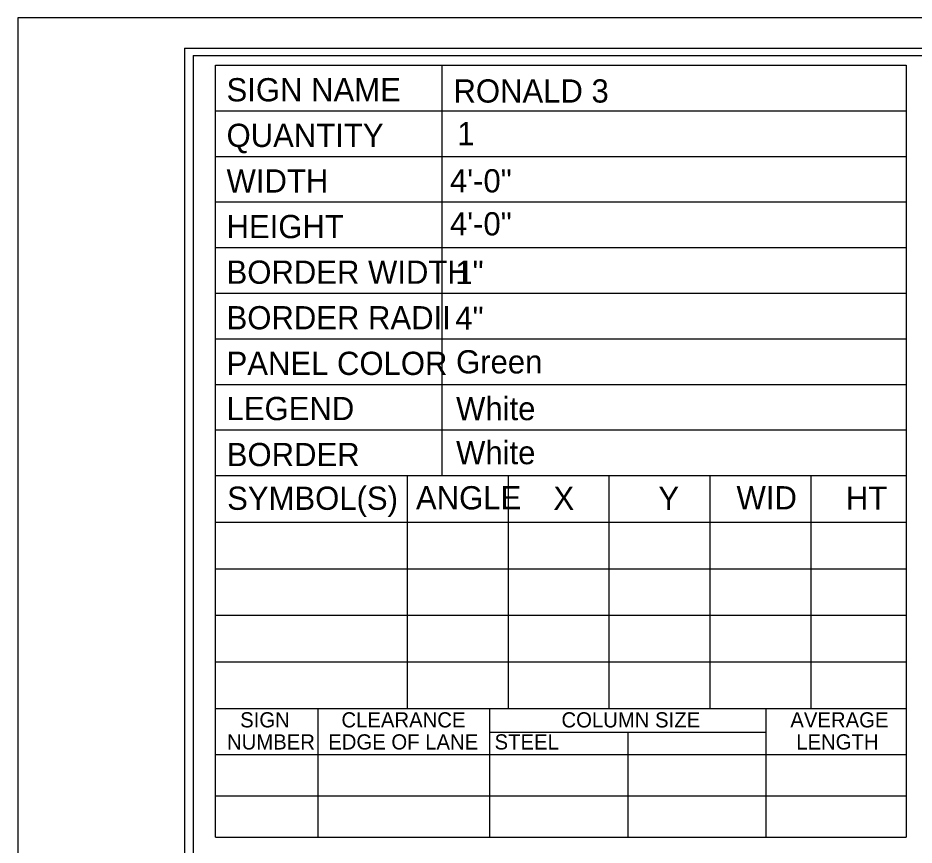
# Model space of a CAD drawing. Extents: x 17890628 to 17890844, y 17897693 to 17898031.
# Drawn here: x 17890700.47 to 17890726.2, y 17897976.07 to 17897999.81 of the extents above; entities that cross this region are included whole.
import ezdxf

# ---------------------------------------------------------------- set-up
doc = ezdxf.new("R2010")
doc.units = 0
for name, color, linetype in [('GSSign', 7, 'Continuous'), ('PlotBorder_dp', 7, 'Continuous'), ('SheetBorder_dp', 7, 'Continuous'), ('SheetLinesMisc2_dp', 7, 'Continuous'), ('TextMinor', 7, 'Continuous')]:
    doc.layers.add(name, color=color, linetype=linetype)

msp = doc.modelspace()

# ---------------------------------------------------------------- linework, layer by layer
at = {"layer": 'PlotBorder_dp'}
msp.add_lwpolyline([(17890700.471, 17897907.61), (17890843.989, 17897907.61), (17890843.989, 17897999.809), (17890700.471, 17897999.809)], close=True, dxfattribs=at)
at = {"layer": 'SheetBorder_dp'}
for q in [(17890705.254, 17897908.479), (17890839.205, 17897998.94)]:
    msp.add_line((17890705.254, 17897998.94), q, dxfattribs=at)
at = {"layer": 'SheetLinesMisc2_dp'}
for p, q in [((17890705.5, 17897998.732), (17890839.233, 17897998.732)), ((17890705.5, 17897998.732), (17890705.5, 17897915.484)), ((17890706.142, 17897976.3), (17890706.142, 17897998.455)), ((17890706.142, 17897998.455), (17890725.973, 17897998.455)), ((17890712.643, 17897998.455), (17890712.643, 17897986.674)), ((17890725.973, 17897998.455), (17890725.973, 17897976.3)), ((17890706.142, 17897997.146), (17890725.973, 17897997.146)), ((17890706.142, 17897995.837), (17890725.973, 17897995.837)), ((17890706.142, 17897994.529), (17890725.973, 17897994.529)), ((17890706.142, 17897993.22), (17890725.973, 17897993.22)), ((17890706.142, 17897991.911), (17890725.973, 17897991.911)), ((17890706.142, 17897990.603), (17890725.973, 17897990.603)), ((17890706.142, 17897989.294), (17890716.057, 17897989.294)), ((17890716.057, 17897989.294), (17890725.973, 17897989.294)), ((17890706.142, 17897987.986), (17890716.057, 17897987.986)), ((17890716.057, 17897987.986), (17890725.973, 17897987.986)), ((17890706.141, 17897986.674), (17890725.973, 17897986.674)), ((17890711.644, 17897986.674), (17890711.644, 17897979.993)), ((17890714.542, 17897986.674), (17890714.542, 17897979.993)), ((17890717.44, 17897986.674), (17890717.44, 17897979.993)), ((17890720.337, 17897986.674), (17890720.337, 17897979.993)), ((17890723.235, 17897986.674), (17890723.235, 17897979.993)), ((17890706.141, 17897985.338), (17890725.973, 17897985.338)), ((17890706.141, 17897984.002), (17890725.973, 17897984.002)), ((17890706.141, 17897982.666), (17890725.973, 17897982.666)), ((17890706.141, 17897981.329), (17890725.973, 17897981.329)), ((17890706.141, 17897979.993), (17890725.973, 17897979.993)), ((17890709.08, 17897979.993), (17890709.08, 17897976.3)), ((17890714.015, 17897979.993), (17890714.015, 17897976.3)), ((17890721.947, 17897979.993), (17890721.947, 17897976.3)), ((17890714.015, 17897979.313), (17890721.947, 17897979.313)), ((17890717.981, 17897979.313), (17890717.981, 17897976.3)), ((17890706.141, 17897978.673), (17890725.973, 17897978.673)), ((17890706.141, 17897977.487), (17890725.973, 17897977.487)), ((17890706.142, 17897976.3), (17890725.973, 17897976.3))]:
    msp.add_line(p, q, dxfattribs=at)

# ---------------------------------------------------------------- texts
at = {"layer": 'GSSign'}
for s, height, p in [('RONALD 3', 0.6667, (17890712.976, 17897997.38)), ('1', 0.667, (17890713.084, 17897996.156)), ('4\'-0"', 0.6667, (17890712.874, 17897994.802)), ('4\'-0"', 0.6667, (17890712.874, 17897993.568)), ('1"', 0.6667, (17890713.029, 17897992.172)), ('4"', 0.6667, (17890713.029, 17897990.861)), ('Green', 0.6667, (17890713.05, 17897989.607)), ('White', 0.6667, (17890713.05, 17897988.265)), ('White', 0.6667, (17890713.05, 17897987.001))]:
    msp.add_text(s, height=height, dxfattribs=at).set_placement(p)
at = {"layer": 'TextMinor'}
for s, height, p in [('SIGN NAME', 0.6667, (17890706.461, 17897997.415)), ('QUANTITY', 0.6667, (17890706.461, 17897996.106)), ('WIDTH', 0.6667, (17890706.461, 17897994.798)), ('HEIGHT', 0.6667, (17890706.461, 17897993.489)), ('BORDER WIDTH', 0.66667, (17890706.461, 17897992.18)), ('BORDER RADII', 0.66667, (17890706.461, 17897990.872)), ('PANEL COLOR', 0.66667, (17890706.461, 17897989.563)), ('LEGEND', 0.6667, (17890706.461, 17897988.266)), ('BORDER', 0.6667, (17890706.467, 17897986.946)), ('SYMBOL(S)', 0.6667, (17890706.478, 17897985.692)), ('ANGLE', 0.6667, (17890711.899, 17897985.705)), ('X', 0.667, (17890715.846, 17897985.692)), ('Y', 0.667, (17890718.859, 17897985.692)), ('WID', 0.6667, (17890721.103, 17897985.705)), ('HT', 0.6667, (17890724.244, 17897985.693)), ('SIGN', 0.4357, (17890706.852, 17897979.448)), ('CLEARANCE', 0.4357, (17890709.759, 17897979.447)), ('COLUMN SIZE', 0.43573, (17890716.077, 17897979.447)), ('AVERAGE', 0.4357, (17890722.648, 17897979.447)), ('NUMBER', 0.4357, (17890706.473, 17897978.814)), ('EDGE OF LANE', 0.43573, (17890709.38, 17897978.814)), ('STEEL    ', 0.4357, (17890714.156, 17897978.814)), ('LENGTH', 0.4357, (17890722.817, 17897978.814))]:
    msp.add_text(s, height=height, dxfattribs=at).set_placement(p)

doc.saveas('drawing.dxf')
